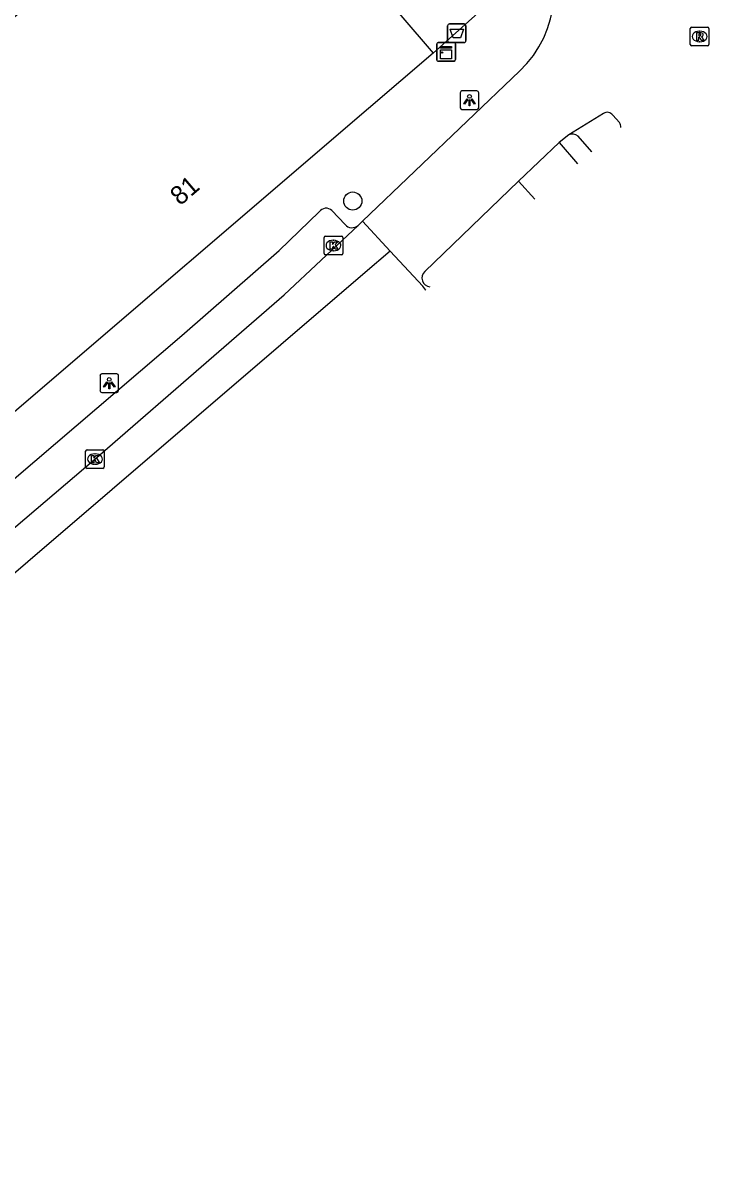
# Model space of a CAD drawing. Extents: x 161772 to 163123, y 383092 to 383917.
# Drawn here: x 162481.4 to 162518.3, y 383336.7 to 383398.9 of the extents above; entities that cross this region are included whole.
import ezdxf

# ---------------------------------------------------------------- set-up
doc = ezdxf.new("R2010")
doc.units = 0
for name, color, linetype in [('IMGEO_Afvalbak', 7, 'Continuous'), ('IMGEO_Boom', 7, 'Continuous'), ('IMGEO_Kast', 7, 'Continuous'), ('IMGEO_Kolk', 7, 'Continuous'), ('IMGEO_Lichtpunt', 7, 'Continuous'), ('IMGEO_Pand', 7, 'Continuous'), ('IMGEO_Pand_nummerreeks', 7, 'Continuous'), ('IMGEO_Rijbaan_lokaal_gesloten', 7, 'Continuous'), ('IMGEO_Rioolput', 7, 'Continuous'), ('IMGEO_Verkeerseiland_gesloten', 7, 'Continuous'), ('IMGEO_Voetpad_open', 7, 'Continuous')]:
    doc.layers.add(name, color=color, linetype=linetype)

msp = doc.modelspace()

# ---------------------------------------------------------------- linework, layer by layer
at = {"layer": 'IMGEO_Afvalbak'}
for p, q in [((162504.262, 383397.924), (162504.262, 383398.724)), ((162504.262, 383398.724), (162504.262, 383397.924)), ((162504.362, 383398.824), (162505.152, 383398.824)), ((162505.152, 383398.824), (162504.362, 383398.824)), ((162505.252, 383398.724), (162505.252, 383397.924)), ((162505.252, 383397.924), (162505.252, 383398.724)), ((162505.152, 383397.824), (162504.362, 383397.824)), ((162504.362, 383397.824), (162505.152, 383397.824))]:
    msp.add_line(p, q, dxfattribs=at)
msp.add_lwpolyline([(162504.405, 383398.538), (162505.109, 383398.538), (162504.96, 383398.068), (162504.554, 383398.068), (162504.405, 383398.538)], dxfattribs=at)
for centre, start, end in [((162504.362, 383398.724), 90, 180), ((162504.362, 383398.724), 90, 180), ((162505.152, 383398.724), 0, 90), ((162505.152, 383398.724), 360, 90), ((162504.362, 383397.924), 180, 270), ((162504.362, 383397.924), 180, 270), ((162505.152, 383397.924), 270, 0), ((162505.152, 383397.924), 270, 0)]:
    msp.add_arc(centre, 0.1, start, end, dxfattribs=at)
at = {"layer": 'IMGEO_Boom'}
msp.add_circle((162499.161, 383389.293), 0.489, dxfattribs=at)
at = {"layer": 'IMGEO_Kast'}
for p, q in [((162503.682, 383396.896), (162503.682, 383397.737)), ((162503.682, 383397.737), (162503.682, 383396.896)), ((162503.757, 383397.821), (162504.598, 383397.821)), ((162504.598, 383397.821), (162503.757, 383397.821)), ((162504.682, 383397.746), (162504.682, 383396.905)), ((162504.682, 383396.905), (162504.682, 383397.746)), ((162504.607, 383396.821), (162503.766, 383396.821)), ((162503.766, 383396.821), (162504.607, 383396.821))]:
    msp.add_line(p, q, dxfattribs=at)
for points in [[(162503.877, 383397.611), (162504.477, 383397.611), (162504.477, 383397.526), (162503.877, 383397.526), (162503.877, 383397.611)], [(162503.877, 383397.436), (162504.477, 383397.436), (162504.477, 383396.947), (162503.877, 383396.947), (162503.877, 383397.436)]]:
    msp.add_lwpolyline(points, dxfattribs=at)
msp.add_circle((162503.961, 383397.285), 0.0377, dxfattribs=at)
for centre, start, end in [((162503.76, 383397.743), 92.4484, 184.28452), ((162503.76, 383397.743), 92.4484, 184.28452), ((162504.604, 383397.743), 2.4484, 94.28452), ((162504.604, 383397.743), 2.4484, 94.28452), ((162503.76, 383396.899), 182.4484, 274.28452), ((162503.76, 383396.899), 182.4484, 274.28452), ((162504.604, 383396.899), 272.4484, 4.28452), ((162504.604, 383396.899), 272.4484, 4.28452)]:
    msp.add_arc(centre, 0.0779, start, end, dxfattribs=at)
at = {"layer": 'IMGEO_Kolk'}
for p, q in [((162497.621, 383386.478), (162497.621, 383387.33)), ((162497.696, 383387.404), (162498.548, 383387.404)), ((162498.109, 383387.184), (162498.134, 383387.184)), ((162498.622, 383387.33), (162498.622, 383386.478)), ((162498.132, 383386.624), (162498.107, 383386.624)), ((162498.548, 383386.404), (162497.696, 383386.404)), ((162484.79, 383374.987), (162484.79, 383375.839)), ((162484.865, 383375.913), (162485.717, 383375.913)), ((162485.278, 383375.693), (162485.303, 383375.693)), ((162485.791, 383375.839), (162485.791, 383374.987)), ((162485.717, 383374.913), (162484.865, 383374.913)), ((162485.301, 383375.133), (162485.276, 383375.133))]:
    msp.add_line(p, q, dxfattribs=at)
for points in [[(162497.621, 383386.478), (162497.621, 383387.33)], [(162497.696, 383387.404), (162498.548, 383387.404)], [(162498.622, 383387.33), (162498.622, 383386.478)], [(162497.942, 383387.104), (162498.065, 383387.104), (162498.065, 383386.953), (162498.195, 383387.104), (162498.359, 383387.104), (162498.213, 383386.953), (162498.366, 383386.704), (162498.214, 383386.704), (162498.129, 383386.868), (162498.065, 383386.801), (162498.065, 383386.704), (162497.942, 383386.704), (162497.942, 383387.104)], [(162498.548, 383386.404), (162497.696, 383386.404)], [(162484.79, 383374.987), (162484.79, 383375.839)], [(162484.865, 383375.913), (162485.717, 383375.913)], [(162485.111, 383375.613), (162485.234, 383375.613), (162485.234, 383375.462), (162485.364, 383375.613), (162485.528, 383375.613), (162485.382, 383375.462), (162485.535, 383375.213), (162485.383, 383375.213), (162485.298, 383375.377), (162485.234, 383375.31), (162485.234, 383375.213), (162485.111, 383375.213), (162485.111, 383375.613)], [(162485.791, 383375.839), (162485.791, 383374.987)], [(162485.717, 383374.913), (162484.865, 383374.913)]]:
    msp.add_lwpolyline(points, dxfattribs=at)
for centre, start, end in [((162497.698, 383387.328), 91.55205, 178.44795), ((162497.698, 383387.328), 91.55205, 178.44795), ((162498.546, 383387.328), 1.55205, 88.44795), ((162498.546, 383387.328), 1.55205, 88.44795), ((162497.698, 383386.48), 181.55205, 268.44795), ((162497.698, 383386.48), 181.55205, 268.44795), ((162498.546, 383386.48), 271.55205, 358.44795), ((162498.546, 383386.48), 271.55205, 358.44795), ((162484.867, 383375.837), 91.55205, 178.44795), ((162484.867, 383375.837), 91.55205, 178.44795), ((162485.715, 383375.837), 1.55205, 88.44795), ((162485.715, 383375.837), 1.55205, 88.44795), ((162484.867, 383374.989), 181.55205, 268.44795), ((162484.867, 383374.989), 181.55205, 268.44795), ((162485.715, 383374.989), 271.55205, 358.44795), ((162485.715, 383374.989), 271.55205, 358.44795)]:
    msp.add_arc(centre, 0.0765, start, end, dxfattribs=at)
for centre, major_axis, ratio, start_param, end_param in [((162498.108, 383386.904), (-0.387, 0.002), 0.722429, 4.712389, 7.853982), ((162498.133, 383386.904), (-0.39, 0.002), 0.717154, 1.570796, 4.712389), ((162485.277, 383375.413), (-0.387, 0.002), 0.722429, 4.712389, 7.853982), ((162485.302, 383375.413), (-0.39, 0.002), 0.717154, 1.570796, 4.712389)]:
    msp.add_ellipse(centre, major_axis=major_axis, ratio=ratio, start_param=start_param, end_param=end_param, dxfattribs=at)
at = {"layer": 'IMGEO_Lichtpunt'}
for p, q in [((162504.941, 383395.126), (162504.941, 383394.319)), ((162504.941, 383395.126), (162504.941, 383394.319)), ((162505.843, 383395.221), (162505.035, 383395.221)), ((162505.843, 383395.221), (162505.035, 383395.221)), ((162505.937, 383394.319), (162505.937, 383395.126)), ((162505.937, 383394.319), (162505.937, 383395.126)), ((162505.035, 383394.225), (162505.843, 383394.225)), ((162505.035, 383394.225), (162505.843, 383394.225)), ((162485.563, 383379.903), (162485.563, 383379.096)), ((162485.563, 383379.903), (162485.563, 383379.096)), ((162486.465, 383379.998), (162485.657, 383379.998)), ((162486.465, 383379.998), (162485.657, 383379.998)), ((162486.559, 383379.096), (162486.559, 383379.903)), ((162486.559, 383379.096), (162486.559, 383379.903)), ((162485.657, 383379.002), (162486.465, 383379.002)), ((162485.657, 383379.002), (162486.465, 383379.002))]:
    msp.add_line(p, q, dxfattribs=at)
for points in [[(162505.315, 383394.79), (162505.354, 383394.762), (162505.166, 383394.5), (162505.128, 383394.527), (162505.315, 383394.79)], [(162505.417, 383394.742), (162505.464, 383394.742), (162505.464, 383394.42), (162505.417, 383394.42), (162505.417, 383394.742)], [(162505.527, 383394.762), (162505.565, 383394.789), (162505.752, 383394.527), (162505.713, 383394.499), (162505.527, 383394.762)], [(162485.937, 383379.567), (162485.976, 383379.539), (162485.788, 383379.277), (162485.75, 383379.304), (162485.937, 383379.567)], [(162486.039, 383379.519), (162486.086, 383379.519), (162486.086, 383379.197), (162486.039, 383379.197), (162486.039, 383379.519)], [(162486.149, 383379.539), (162486.187, 383379.566), (162486.374, 383379.304), (162486.335, 383379.276), (162486.149, 383379.539)]]:
    msp.add_lwpolyline(points, dxfattribs=at)
for centre in [(162505.44, 383394.924), (162486.062, 383379.701)]:
    msp.add_circle(centre, 0.0994, dxfattribs=at)
for centre, start, end in [((162505.035, 383395.126), 90, 180), ((162505.035, 383395.126), 90, 180), ((162505.843, 383395.126), 0, 90), ((162505.843, 383395.126), 0, 90), ((162505.035, 383394.319), 180, 270), ((162505.035, 383394.319), 180, 270), ((162505.843, 383394.319), 270, 0), ((162505.843, 383394.319), 270, 360), ((162485.657, 383379.903), 90, 180), ((162485.657, 383379.903), 90, 180), ((162486.465, 383379.903), 0, 90), ((162486.465, 383379.903), 0, 90), ((162485.657, 383379.096), 180, 270), ((162485.657, 383379.096), 180, 270), ((162486.465, 383379.096), 270, 0), ((162486.465, 383379.096), 270, 360)]:
    msp.add_arc(centre, 0.0946, start, end, dxfattribs=at)
at = {"layer": 'IMGEO_Pand'}
for points in [[(162474.088, 383385.068), (162478.415, 383388.739), (162474.314, 383393.573), (162489.4, 383406.371), (162493.01, 383409.473), (162500, 383401.316), (162503.481, 383397.254)], [(162503.481, 383397.254), (162500, 383394.271), (162480.594, 383377.64)]]:
    msp.add_lwpolyline(points, dxfattribs=at)
at = {"layer": 'IMGEO_Rijbaan_lokaal_gesloten'}
for points in [[(162508.138, 383396.281), (162499.683, 383388.214)], [(162512.647, 383394.013), (162510.785, 383392.863)], [(162513.513, 383393.514), (162513.148, 383393.907)], [(162510.785, 383392.863), (162510.257, 383392.438)], [(162508.081, 383390.361), (162510.257, 383392.438)], [(162508.081, 383390.361), (162503.036, 383385.509)], [(162464.826, 383358.018), (162467.172, 383359.987), (162485.292, 383375.412), (162491.686, 383380.972), (162495.478, 383384.248), (162499.449, 383387.988)], [(162499.449, 383387.988), (162499.683, 383388.214)], [(162499.683, 383388.214), (162501.18, 383386.596)], [(162501.18, 383386.596), (162499.827, 383385.459), (162477.128, 383365.985), (162459.036, 383350.651), (162175.227, 383109.464), (162171.607, 383105.25), (162169.364, 383100.909), (162168.706, 383099.067), (162168.602, 383098.586)], [(162503.092, 383384.494), (162503.092, 383384.494), (162502.922, 383384.713), (162501.18, 383386.596)]]:
    msp.add_lwpolyline(points, dxfattribs=at)
for centre, radius, start, end in [((162503.873, 383400.703), 6.144, 313.95972, 35.91538), ((162512.842, 383393.697), 0.372, 34.50238, 121.60505), ((162513.114, 383393.265), 0.47, 358.97119, 31.91599), ((162513.128, 383393.259), 0.456, 359.7716, 359.80125), ((162503.356, 383385.155), 0.477, 132.14317, 265.05815)]:
    msp.add_arc(centre, radius, start, end, dxfattribs=at)
at = {"layer": 'IMGEO_Rioolput'}
for p, q in [((162517.318, 383397.723), (162517.318, 383398.575)), ((162517.393, 383398.649), (162518.245, 383398.649)), ((162517.806, 383398.429), (162517.831, 383398.429)), ((162518.319, 383398.575), (162518.319, 383397.723)), ((162517.829, 383397.869), (162517.804, 383397.869)), ((162518.245, 383397.649), (162517.393, 383397.649))]:
    msp.add_line(p, q, dxfattribs=at)
for points in [[(162517.318, 383397.723), (162517.318, 383398.575)], [(162517.393, 383398.649), (162518.245, 383398.649)], [(162518.319, 383398.575), (162518.319, 383397.723)], [(162517.907, 383398.347), (162517.655, 383398.349), (162517.655, 383397.949)], [(162517.655, 383397.949), (162517.779, 383397.949), (162517.779, 383398.111), (162517.79, 383398.111)], [(162517.833, 383398.268), (162517.779, 383398.268), (162517.779, 383398.187)], [(162517.779, 383398.187), (162517.831, 383398.187)], [(162517.837, 383398.082), (162517.908, 383397.949), (162518.048, 383397.949), (162517.983, 383398.075)], [(162518.245, 383397.649), (162517.393, 383397.649)]]:
    msp.add_lwpolyline(points, dxfattribs=at)
for centre, radius, start, end in [((162517.395, 383398.573), 0.0765, 91.55205, 178.44795), ((162517.395, 383398.573), 0.0765, 91.55205, 178.44795), ((162518.243, 383398.573), 0.0765, 1.55205, 88.44795), ((162518.243, 383398.573), 0.0765, 1.55205, 88.44795), ((162517.789, 383398.058), 0.0533, 26.02933, 88.69889), ((162517.815, 383398.376), 0.19, 274.7715, 282.96867), ((162517.839, 383398.172), 0.0964, 77.00612, 93.18647), ((162517.853, 383398.229), 0.0378, 276.66336, 79.67722), ((162517.906, 383398.237), 0.109, 350.36119, 89.41601), ((162517.904, 383398.237), 0.112, 277.58423, 350.98172), ((162517.888, 383398.022), 0.108, 29.51342, 73.79051), ((162517.395, 383397.725), 0.0765, 181.55205, 268.44795), ((162517.395, 383397.725), 0.0765, 181.55205, 268.44795), ((162518.243, 383397.725), 0.0765, 271.55205, 358.44795), ((162518.243, 383397.725), 0.0765, 271.55205, 358.44795)]:
    msp.add_arc(centre, radius, start, end, dxfattribs=at)
for centre, major_axis, ratio, start_param, end_param in [((162517.805, 383398.149), (-0.387, 0.002), 0.722429, 4.712389, 7.853982), ((162517.83, 383398.149), (-0.39, 0.002), 0.717154, 1.570796, 4.712389)]:
    msp.add_ellipse(centre, major_axis=major_axis, ratio=ratio, start_param=start_param, end_param=end_param, dxfattribs=at)
at = {"layer": 'IMGEO_Verkeerseiland_gesloten'}
msp.add_lwpolyline([(162512.018, 383391.949), (162512.018, 383391.949), (162511.279, 383392.79)], dxfattribs=at)
msp.add_arc((162510.968, 383392.394), 0.504, 51.86993, 111.31816, dxfattribs=at)
at = {"layer": 'IMGEO_Voetpad_open'}
for points in [[(162503.481, 383397.254), (162506.255, 383399.731)], [(162510.257, 383392.438), (162511.248, 383391.306), (162511.248, 383391.306)], [(162508.954, 383389.39), (162508.954, 383389.39), (162508.081, 383390.361)], [(162476.359, 383370.433), (162489.959, 383382.059), (162495.209, 383386.638), (162497.356, 383388.716)], [(162498.032, 383388.786), (162498.748, 383388.038)]]:
    msp.add_lwpolyline(points, dxfattribs=at)
for centre, radius, start, end in [((162497.725, 383388.454), 0.452, 47.19842, 144.62543), ((162499.122, 383388.344), 0.484, 219.31144, 312.52895)]:
    msp.add_arc(centre, radius, start, end, dxfattribs=at)

# ---------------------------------------------------------------- texts
at = {"layer": 'IMGEO_Pand_nummerreeks'}
msp.add_text('81', height=1, rotation=40.61125, dxfattribs=at).set_placement((162489.874, 383389.013))

doc.saveas('drawing.dxf')
